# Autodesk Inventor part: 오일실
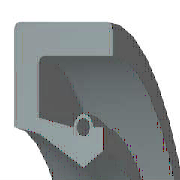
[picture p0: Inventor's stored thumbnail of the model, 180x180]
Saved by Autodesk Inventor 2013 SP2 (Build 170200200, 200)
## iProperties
IsCustomPart: 0
Created: 2016-05
Part Number: 오일실
Material: 고무
Description: 오일-실
Document SubType Name: Modeling
Standard: KS B 2804
Designer: mduedu
Standards Organization: KS
Language: ko-KR
Size Designation: S - 17 30 8
Categories: <MemberInstance><Categories><Category DisplayName="샤프트 부품" InternalName="7f7aeb1f-a693-4053-b835-cee3144e0d98" Mnemonic="SHFT"><Category DisplayName="실링" Intern
Density: 0.93 g/cm^3
Author: mduedu
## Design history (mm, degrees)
revolve "본체" stored, may be unused: angle "d17" = 90 deg
revolve "스프링1" stored, may be unused: angle "d18" = 90 deg
body "Solid1"
sketch "스케치1"
  geometry: L1 (0, 15)-(8, 15); L2 (8, 15)-(8, 13.75); L3 (8, 13.75)-(1.75, 13.75); L4 (0, 15)-(0, 10.6); L5 (0, 10.6)-(1.75, 10.25); L6 (1.75, 10.25)-(4.9, 8.5); L7 (4.9, 8.5)-(0, 8.5); L8 (6.3, 9.375)-(6.3, 10.6); L9 (0, 0)-(9.586, 0) reference; L10 (4.9, 8.5)-(6.3, 9.375); L11 (0, 18)-(0, -3) reference; L12 (-1.917, 0)-(11.503, 0) reference; L13 (4.2, 10.6)-(1.75, 11.09); L14 (1.75, 11.09)-(1.75, 13.75); L15 (6.3, 10.6)-(5.6, 10.6); C1 r 0.455 at (4.9, 10.6); A1 r 0.7 centre (4.9, 10.6) between (5.6, 10.6) and (4.2, 10.6)
  constraints: 26 end point, 5 horizontal alignment, 4 perpendicular, 2 centre point, 2 collinear, 2 horizontal, 2 parallel, 2 point on circle, 2 point on line, 2 vertical alignment, 1 coincident
  dimensions: "d0" = 30 diameter of L1 L9 (= SD2); "d1" = 18.75 diameter of L8.start L9 (= ABDM); "d2" = 1.25 distance of L1.end L2.end (computed from SD); "d3" = 0.91 diameter of C1 (= SPDI); "d4" = 1.4 diameter of A1 (= SPDA); "d5" = 17 diameter of L6.end L9 (= NND); "d6" = 20.5 diameter of L5.end L9 (= TKDM); "d7" = 21.2 diameter of L4.end L9 (= HLDM); "d8" = 4.9 distance from line of C1.centre L4 (= SPDST); "d9" = 6.3 distance between parallel lines of L8 L4 (= SDI); "d10" = 8 distance between parallel lines of L2 L4 (= SWDT); "d12" = 1.75 distance between parallel lines of L14 L4 (= SD)
fillet "모깎기1" dims "d11" = 0.3 (= RR)
other parameters: "SD2" = 30 [user parameter; used in 1 equation term], "SWDT" = 8 [user parameter; used in 1 equation term], "RR" = 0.3 [user parameter; used in 1 equation term], "SD" = 1.75 [user parameter; used in 2 equation terms], "NND" = 17 [user parameter; used in 1 equation term], "SPDA" = 1.4 [user parameter; used in 1 equation term], "SPDI" = 0.91 [user parameter; used in 1 equation term], "TKDM" = 20.5 [user parameter; used in 1 equation term], "HLDM" = 21.2 [user parameter; used in 1 equation term], "ABDM" = 18.75 [user parameter; used in 1 equation term], "SDI" = 6.3 [user parameter; used in 1 equation term], "SPDST" = 4.9 [user parameter; used in 1 equation term], "d13" = 0, "d14" = 0, "d15" = 0, "LAB" = 0.35 [user parameter]
